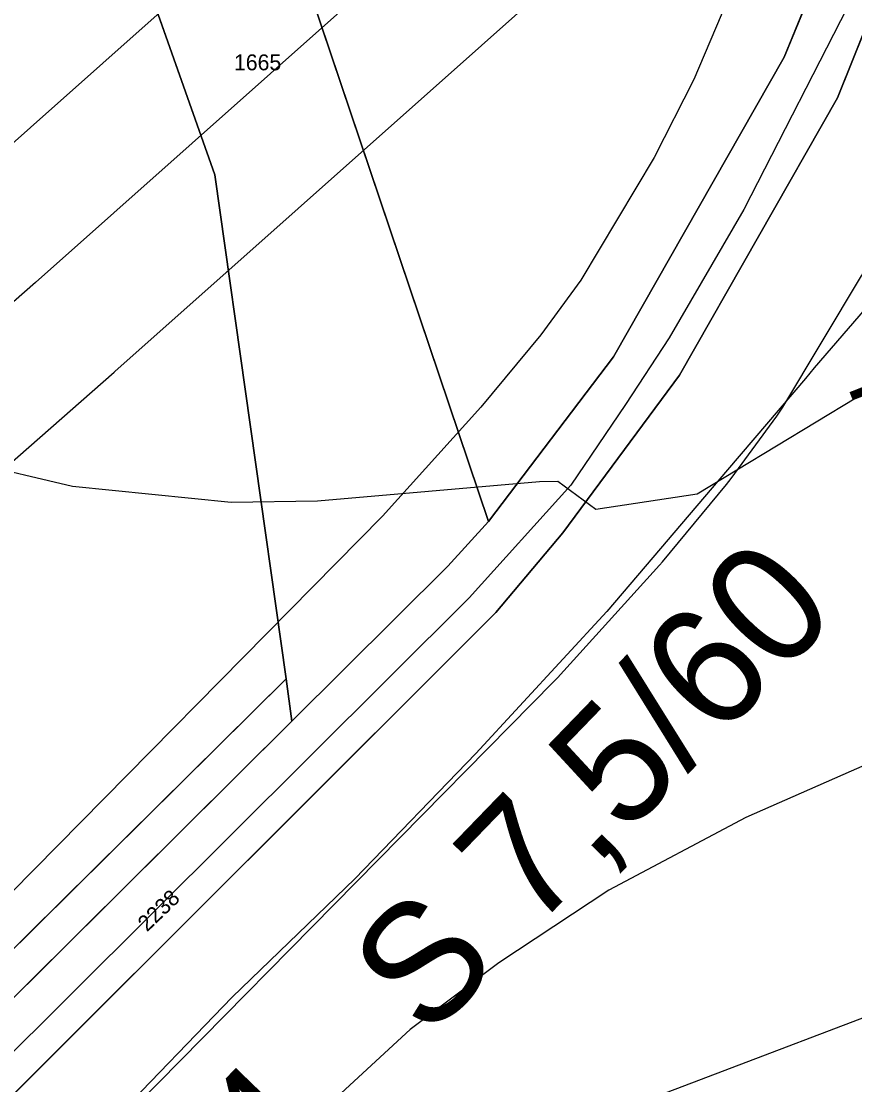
# Model space of a CAD drawing. Extents: x -706130 to -698555, y -971544 to -967260.
# Drawn here: x -704475.2 to -704370.4, y -971218.1 to -971084.3 of the extents above; entities that cross this region are included whole.
import ezdxf

# ---------------------------------------------------------------- set-up
doc = ezdxf.new("R2010")
doc.units = 0
for name, color, linetype in [('BPEJ hranice S', 7, 'Continuous'), ('BPEJ I-II trida ochrany S', 7, 'Continuous'), ('Elektro VVN nadzemní 110 S', 7, 'Continuous'), ('KN_Hranice_parcel', 7, 'Continuous'), ('KN_Parcelni cisla', 7, 'Continuous'), ('KN_Polygon parcely', 7, 'Continuous'), ('KN_POZEMKY_14_OSTATNI PLOCHA', 7, 'Continuous'), ('KN_POZEMKY_2_ORNA PUDA', 7, 'Continuous'), ('KN_VYUZITI_16_ostatni plocha_silnice', 7, 'Continuous'), ('Komunikace III třídy osy S', 7, 'Continuous'), ('Komunikace popis trid a kategorie popis S', 7, 'Continuous'), ('OP ELE VN_VVN_trafostanice', 7, 'Continuous'), ('OP silnic S', 7, 'Continuous'), ('Plochy doprava silniční - silnice III třídy S', 7, 'Continuous'), ('Plochy zemědělské všeobecné CELEK S', 7, 'Continuous'), ('Regulační bloky v krajině S', 7, 'Continuous'), ('Regulační bloky zastavěné S', 7, 'Continuous'), ('Spoje_dálkový komunikační kabel S', 7, 'Continuous'), ('Trasy cykloturistické N', 7, 'Continuous'), ('USES_nadregionalni_popis N', 7, 'Continuous'), ('VÝŠKOPIS_vrstevnice hlavní', 7, 'Continuous')]:
    doc.layers.add(name, color=color, linetype=linetype)

msp = doc.modelspace()

# ---------------------------------------------------------------- linework, layer by layer
at = {"layer": 'BPEJ hranice S'}
msp.add_lwpolyline([(-704401.02, -971221.7), (-704353.59, -971203.67), (-704319.45, -971190.38), (-704294.46, -971180.26), (-704291.01, -971178.87), (-704279.61, -971174.25), (-704252.66, -971161.61)], dxfattribs=at)
msp.add_lwpolyline([(-704401.02, -971221.7), (-704353.59, -971203.67), (-704319.45, -971190.38), (-704294.46, -971180.26), (-704291.01, -971178.87), (-704279.61, -971174.25), (-704252.66, -971161.61)], dxfattribs=at)
at = {"layer": 'BPEJ I-II trida ochrany S'}
for p, q in [((-704379.24, -971088.79), (-704371.03, -971068.69)), ((-704363.75, -971071.95), (-704372.53, -971093.91)), ((-704400.72, -971126.52), (-704379.24, -971088.79)), ((-704372.53, -971093.91), (-704392.41, -971128.82)), ((-704416.46, -971147.21), (-704400.72, -971126.52)), ((-704392.41, -971128.82), (-704407.11, -971148.63)), ((-704421.56, -971152.85), (-704416.46, -971147.21)), ((-704407.11, -971148.63), (-704415.53, -971158.66)), ((-704441.18, -971172.34), (-704421.56, -971152.85)), ((-704415.53, -971158.66), (-704506.42, -971249.39)), ((-704555.17, -971285.57), (-704441.18, -971172.34))]:
    msp.add_line(p, q, dxfattribs=at)
msp.add_lwpolyline([(-704466.47, -971257.76), (-704444.65, -971240.68), (-704401.02, -971221.7), (-704353.59, -971203.67), (-704319.45, -971190.38)], dxfattribs=at)
at = {"layer": 'Elektro VVN nadzemní 110 S'}
for points in [[(-704345.55, -970983.3), (-704483.21, -971105.76), (-704640.23, -971243.74), (-704805.87, -971389.21), (-704875.36, -971405.35)], [(-704335.28, -970994.23), (-704335.46, -970994.39), (-704473.45, -971117.14), (-704630.39, -971255.05), (-704798.95, -971403.11), (-704854.09, -971415.88)]]:
    msp.add_lwpolyline(points, dxfattribs=at)
at = {"layer": 'KN_Hranice_parcel'}
for p, q in [((-704441.18, -971172.34), (-704441.93, -971167)), ((-704555.17, -971285.57), (-704441.18, -971172.34))]:
    msp.add_line(p, q, dxfattribs=at)
for points in [[(-704480.71, -970987.86), (-704466.38, -971059.78), (-704450.89, -971103.61), (-704441.93, -971167)], [(-704416.46, -971147.21), (-704400.72, -971126.52), (-704379.24, -971088.79), (-704371.03, -971068.69), (-704363.13, -971044.43), (-704360.7, -971028.37), (-704358.88, -970998.11)], [(-704352.25, -971025.04), (-704354.41, -971041.91), (-704363.75, -971071.95), (-704372.53, -971093.91), (-704392.41, -971128.82), (-704407.11, -971148.63), (-704415.53, -971158.66), (-704506.42, -971249.39), (-704551.5, -971295.37), (-704580.53, -971322.96), (-704605.87, -971343.56)], [(-704450.87, -971043.52), (-704450.23, -971047.02), (-704416.46, -971147.21)], [(-704441.18, -971172.34), (-704421.56, -971152.85), (-704416.46, -971147.21)], [(-704441.93, -971167), (-704549.29, -971273.33), (-704555.17, -971285.57)]]:
    msp.add_lwpolyline(points, dxfattribs=at)
at = {"layer": 'KN_Polygon parcely'}
for points in [[(-704506.42, -971249.39), (-704415.53, -971158.66), (-704407.11, -971148.63), (-704392.41, -971128.82), (-704372.53, -971093.91), (-704363.75, -971071.95), (-704354.41, -971041.91), (-704352.25, -971025.04), (-704351.58, -971019.76), (-704351.31, -971017.68), (-704350.69, -971011.84), (-704350.44, -971008.36), (-704350.59, -970954.64), (-704350.71, -970916.39), (-704355.73, -970900.46), (-704376.72, -970873.06), (-704385.45, -970859.24), (-704393.06, -970832.89), (-704393.81, -970830.29), (-704396.32, -970808.97), (-704395, -970781.85), (-704385.12, -970737.85), (-704377.41, -970702.19)], [(-704389.28, -970704.44), (-704391.73, -970719.71), (-704394.94, -970736.25), (-704402.86, -970780.15), (-704405.74, -970803.12), (-704402.29, -970834.53), (-704391.88, -970864.93), (-704388.05, -970871.47), (-704383.52, -970877.76), (-704364.6, -970901.09), (-704359.55, -970918.79), (-704358.88, -970998.11), (-704360.7, -971028.37), (-704363.13, -971044.43), (-704371.03, -971068.69), (-704379.24, -971088.79), (-704400.72, -971126.52), (-704416.46, -971147.21), (-704421.56, -971152.85), (-704441.18, -971172.34), (-704555.17, -971285.57)], [(-704347.25, -971251.15), (-704280.58, -971216.79), (-704337.74, -971066.33), (-704352.25, -971025.04), (-704354.41, -971041.91), (-704363.75, -971071.95), (-704372.53, -971093.91), (-704392.41, -971128.82), (-704407.11, -971148.63), (-704415.53, -971158.66), (-704506.42, -971249.39)]]:
    msp.add_lwpolyline(points, dxfattribs=at)
for points in [[(-704450.23, -971047.02), (-704416.46, -971147.21), (-704400.72, -971126.52), (-704379.24, -971088.79), (-704371.03, -971068.69), (-704363.13, -971044.43), (-704360.7, -971028.37), (-704358.88, -970998.11), (-704364.9, -970980.93), (-704377.9, -970979.05), (-704388.29, -970984.51), (-704395.98, -970998.1), (-704425.92, -971019.27), (-704448.75, -971041.07), (-704450.87, -971043.52)], [(-704609.43, -971335.09), (-704585.77, -971315.95), (-704567.91, -971298.24), (-704555.17, -971285.57), (-704549.29, -971273.33), (-704441.93, -971167), (-704450.89, -971103.61), (-704466.38, -971059.78), (-704480.71, -970987.86), (-704567.32, -971026.96), (-704576.96, -971042.42), (-704567.8, -971056.89), (-704572.05, -971076.18), (-704593.88, -971059.39), (-704608.77, -971071.6), (-704630.27, -971084.33), (-704701.81, -971105.18), (-704664.8, -971185.41), (-704639.88, -971252.78), (-704622.91, -971298.66)], [(-704480.71, -970987.86), (-704466.38, -971059.78), (-704450.89, -971103.61), (-704441.93, -971167), (-704441.18, -971172.34), (-704421.56, -971152.85), (-704416.46, -971147.21), (-704450.23, -971047.02), (-704450.87, -971043.52), (-704453.52, -971046.59), (-704461.41, -971000.71)], [(-704555.17, -971285.57), (-704441.18, -971172.34), (-704441.93, -971167), (-704549.29, -971273.33)]]:
    msp.add_lwpolyline(points, close=True, dxfattribs=at)
at = {"layer": 'KN_POZEMKY_14_OSTATNI PLOCHA'}
for p, q in [((-704379.24, -971088.79), (-704371.03, -971068.69)), ((-704363.75, -971071.95), (-704372.53, -971093.91)), ((-704400.72, -971126.52), (-704379.24, -971088.79)), ((-704372.53, -971093.91), (-704392.41, -971128.82)), ((-704416.46, -971147.21), (-704400.72, -971126.52)), ((-704392.41, -971128.82), (-704407.11, -971148.63)), ((-704421.56, -971152.85), (-704416.46, -971147.21)), ((-704407.11, -971148.63), (-704415.53, -971158.66)), ((-704441.18, -971172.34), (-704421.56, -971152.85)), ((-704415.53, -971158.66), (-704506.42, -971249.39)), ((-704555.17, -971285.57), (-704441.18, -971172.34))]:
    msp.add_line(p, q, dxfattribs=at)
at = {"layer": 'KN_POZEMKY_2_ORNA PUDA'}
for p, q in [((-704416.46, -971147.21), (-704450.23, -971047.02)), ((-704450.23, -971047.02), (-704416.46, -971147.21)), ((-704466.38, -971059.78), (-704450.89, -971103.61)), ((-704450.89, -971103.61), (-704466.38, -971059.78)), ((-704371.03, -971068.69), (-704379.24, -971088.79)), ((-704372.53, -971093.91), (-704363.75, -971071.95)), ((-704379.24, -971088.79), (-704400.72, -971126.52)), ((-704392.41, -971128.82), (-704372.53, -971093.91)), ((-704450.89, -971103.61), (-704441.93, -971167)), ((-704441.93, -971167), (-704450.89, -971103.61)), ((-704400.72, -971126.52), (-704416.46, -971147.21)), ((-704407.11, -971148.63), (-704392.41, -971128.82)), ((-704416.46, -971147.21), (-704421.56, -971152.85)), ((-704415.53, -971158.66), (-704407.11, -971148.63)), ((-704421.56, -971152.85), (-704441.18, -971172.34)), ((-704506.42, -971249.39), (-704415.53, -971158.66)), ((-704441.93, -971167), (-704549.29, -971273.33)), ((-704549.29, -971273.33), (-704441.93, -971167)), ((-704441.93, -971167), (-704441.18, -971172.34)), ((-704441.18, -971172.34), (-704441.93, -971167)), ((-704441.18, -971172.34), (-704555.17, -971285.57))]:
    msp.add_line(p, q, dxfattribs=at)
at = {"layer": 'KN_VYUZITI_16_ostatni plocha_silnice'}
for p, q in [((-704379.24, -971088.79), (-704371.03, -971068.69)), ((-704363.75, -971071.95), (-704372.53, -971093.91)), ((-704400.72, -971126.52), (-704379.24, -971088.79)), ((-704372.53, -971093.91), (-704392.41, -971128.82)), ((-704416.46, -971147.21), (-704400.72, -971126.52)), ((-704392.41, -971128.82), (-704407.11, -971148.63)), ((-704421.56, -971152.85), (-704416.46, -971147.21)), ((-704407.11, -971148.63), (-704415.53, -971158.66)), ((-704441.18, -971172.34), (-704421.56, -971152.85)), ((-704415.53, -971158.66), (-704506.42, -971249.39)), ((-704555.17, -971285.57), (-704441.18, -971172.34))]:
    msp.add_line(p, q, dxfattribs=at)
at = {"layer": 'Komunikace III třídy osy S'}
msp.add_lwpolyline([(-704383.9, -970867.59), (-704377.82, -970876.88), (-704361.54, -970898.89), (-704358.47, -970903.18), (-704356.68, -970907.27), (-704355.56, -970911.28), (-704354.81, -970918.03), (-704354.43, -970943.3), (-704354.06, -970951.81), (-704353.43, -970976.95), (-704354.18, -971013.72), (-704355.06, -971020.98), (-704356.68, -971031.11), (-704360.23, -971048.09), (-704365.98, -971067.97), (-704370.46, -971080.83), (-704384.34, -971107.98), (-704393.71, -971124.12), (-704399.21, -971132.5), (-704406.09, -971142.66), (-704418.9, -971156.83), (-704519.04, -971256.52)], dxfattribs=at)
at = {"layer": 'OP ELE VN_VVN_trafostanice'}
msp.add_lwpolyline([(-704832.91, -971426.37), (-704795.57, -971417.72), (-704795.07, -971417.6), (-704794.13, -971417.31), (-704793.21, -971416.97), (-704792.32, -971416.56), (-704791.45, -971416.1), (-704790.62, -971415.58), (-704789.82, -971415.01), (-704789.06, -971414.39), (-704789.05, -971414.38), (-704620.49, -971266.32), (-704620.48, -971266.32), (-704463.55, -971128.41), (-704463.48, -971128.35), (-704325.46, -971005.57)], dxfattribs=at)
at = {"layer": 'OP silnic S'}
for points in [[(-704383.6, -971075.07), (-704390.61, -971091.62), (-704395.6, -971101.43), (-704404.82, -971116.84), (-704409.85, -971123.74), (-704417.42, -971132.83), (-704429.81, -971146.53), (-704529.07, -971247.22)], [(-704507.75, -971268.32), (-704408.22, -971167.36), (-704407.77, -971166.89), (-704394.96, -971152.72), (-704394.58, -971152.28), (-704386.49, -971142.57), (-704385.91, -971141.82), (-704380.18, -971133.98), (-704379.43, -971132.83), (-704369.53, -971116.29), (-704369.09, -971115.49), (-704363.63, -971104.75), (-704363.19, -971103.8), (-704355.62, -971085.92), (-704355.34, -971085.2), (-704355.01, -971084.18)]]:
    msp.add_lwpolyline(points, dxfattribs=at)
at = {"layer": 'Plochy doprava silniční - silnice III třídy S'}
for p, q in [((-704371.03, -971068.69), (-704379.24, -971088.79)), ((-704372.53, -971093.91), (-704363.75, -971071.95)), ((-704379.24, -971088.79), (-704400.72, -971126.52)), ((-704392.41, -971128.82), (-704372.53, -971093.91)), ((-704400.72, -971126.52), (-704416.46, -971147.21)), ((-704407.11, -971148.63), (-704392.41, -971128.82)), ((-704416.46, -971147.21), (-704421.56, -971152.85)), ((-704415.53, -971158.66), (-704407.11, -971148.63)), ((-704421.56, -971152.85), (-704441.18, -971172.34)), ((-704506.42, -971249.39), (-704415.53, -971158.66)), ((-704441.18, -971172.34), (-704555.17, -971285.57))]:
    msp.add_line(p, q, dxfattribs=at)
at = {"layer": 'Plochy zemědělské všeobecné CELEK S'}
for p, q in [((-704379.24, -971088.79), (-704373.92, -971075.78)), ((-704369.72, -971086.89), (-704372.53, -971093.91)), ((-704400.72, -971126.52), (-704379.24, -971088.79)), ((-704372.53, -971093.91), (-704392.41, -971128.82)), ((-704416.46, -971147.21), (-704400.72, -971126.52)), ((-704392.41, -971128.82), (-704407.11, -971148.63)), ((-704421.56, -971152.85), (-704416.46, -971147.21)), ((-704407.11, -971148.63), (-704415.53, -971158.66)), ((-704441.18, -971172.34), (-704421.56, -971152.85)), ((-704555.17, -971285.57), (-704441.18, -971172.34))]:
    msp.add_line(p, q, dxfattribs=at)
msp.add_lwpolyline([(-704415.53, -971158.66), (-704506.42, -971249.39), (-704551.5, -971295.37)], dxfattribs=at)
at = {"layer": 'Regulační bloky v krajině S'}
for p, q in [((-704379.24, -971088.79), (-704373.92, -971075.78)), ((-704369.72, -971086.89), (-704372.53, -971093.91)), ((-704400.72, -971126.52), (-704379.24, -971088.79)), ((-704372.53, -971093.91), (-704392.41, -971128.82)), ((-704416.46, -971147.21), (-704400.72, -971126.52)), ((-704392.41, -971128.82), (-704407.11, -971148.63)), ((-704421.56, -971152.85), (-704416.46, -971147.21)), ((-704407.11, -971148.63), (-704415.53, -971158.66)), ((-704441.18, -971172.34), (-704421.56, -971152.85)), ((-704555.17, -971285.57), (-704441.18, -971172.34))]:
    msp.add_line(p, q, dxfattribs=at)
msp.add_lwpolyline([(-704415.53, -971158.66), (-704506.42, -971249.39), (-704551.5, -971295.37)], dxfattribs=at)
at = {"layer": 'Regulační bloky zastavěné S'}
for p, q in [((-704371.03, -971068.69), (-704379.24, -971088.79)), ((-704372.53, -971093.91), (-704363.75, -971071.95)), ((-704379.24, -971088.79), (-704400.72, -971126.52)), ((-704392.41, -971128.82), (-704372.53, -971093.91)), ((-704400.72, -971126.52), (-704416.46, -971147.21)), ((-704407.11, -971148.63), (-704392.41, -971128.82)), ((-704416.46, -971147.21), (-704421.56, -971152.85)), ((-704415.53, -971158.66), (-704407.11, -971148.63)), ((-704421.56, -971152.85), (-704441.18, -971172.34)), ((-704506.42, -971249.39), (-704415.53, -971158.66)), ((-704441.18, -971172.34), (-704555.17, -971285.57))]:
    msp.add_line(p, q, dxfattribs=at)
at = {"layer": 'Spoje_dálkový komunikační kabel S'}
msp.add_lwpolyline([(-704262.53, -970933.9), (-704272.81, -970957.99), (-704283.34, -970981.18), (-704294.54, -971004.28), (-704305.15, -971026.09), (-704314, -971044.35), (-704321.27, -971059.49), (-704327.69, -971071.45), (-704333.94, -971080.22), (-704347.14, -971096.02), (-704361.96, -971112.17), (-704361.96, -971112.18), (-704369.08, -971120.44), (-704375.46, -971127.9), (-704376.59, -971129.23), (-704386.37, -971140.71), (-704401.58, -971158.55), (-704418.05, -971176.41), (-704433.26, -971192.17), (-704448.7, -971207.06), (-704463.53, -971222.43)], dxfattribs=at)
at = {"layer": 'Trasy cykloturistické N'}
msp.add_lwpolyline([(-704506.42, -971249.39), (-704415.53, -971158.66), (-704407.11, -971148.63), (-704392.41, -971128.82), (-704372.53, -971093.91), (-704363.75, -971071.95), (-704354.41, -971041.91), (-704351.58, -971019.76), (-704350.44, -971008.36), (-704350.59, -970954.64), (-704350.71, -970916.39), (-704355.73, -970900.46), (-704376.72, -970873.06), (-704385.45, -970859.24), (-704393.06, -970832.89), (-704393.81, -970830.29), (-704396.32, -970808.97), (-704395, -970781.85), (-704385.12, -970737.85), (-704377.41, -970702.19)], dxfattribs=at)
at = {"layer": 'VÝŠKOPIS_vrstevnice hlavní'}
for points in [[(-704261.36, -971100.01), (-704273.35, -971112.85), (-704287.04, -971125.55), (-704297.17, -971136.1), (-704314.29, -971149.66), (-704323.28, -971157.93), (-704328.56, -971161.07), (-704342.68, -971167.35), (-704365.94, -971176.48), (-704384.06, -971184.47), (-704401.32, -971193.6), (-704415.16, -971202.73), (-704426.29, -971211.15), (-704434.99, -971219.14)], [(-704325.61, -971108.12), (-704345.82, -971119.55), (-704370.22, -971131.68), (-704390.19, -971143.79), (-704402.95, -971145.72), (-704407.72, -971142.18), (-704410.02, -971142.24), (-704437.99, -971144.66), (-704448.83, -971144.81), (-704468.8, -971142.81), (-704481.64, -971139.81)]]:
    msp.add_lwpolyline(points, dxfattribs=at)

# ---------------------------------------------------------------- texts
at = {"layer": 'KN_Parcelni cisla'}
msp.add_text('1665', height=2, dxfattribs=at).set_placement((-704448.48, -971090.45))
msp.add_text('2238', height=2, rotation=44, dxfattribs=at).set_placement((-704459.41, -971198.92))
at = {"layer": 'Komunikace popis trid a kategorie popis S'}
msp.add_text('III/27244   S 7,5/60', height=15, rotation=45.9672, dxfattribs=at).set_placement((-704489.96, -971280.7))
at = {"layer": 'USES_nadregionalni_popis N'}
msp.add_text('NRBK K34B 119/120', height=10, rotation=291.4436, dxfattribs=at).set_placement((-704371.43, -971129.92))

doc.saveas('drawing.dxf')
